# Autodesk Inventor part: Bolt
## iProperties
Shininess: 77.0
Length Units: 11269
Angle Units: 11279
Time Units: 11290
Mass Units: 11283
Length Display Precision: 3
Angle Display Precision: 2
Created: 2002-02
Part Number: Bolt
Document SubType Name: Modeling
Designer: ***
Stock Number: 25
Density: 0.0
Volumn: 0.0
Area: 0.0
PropertySet Name: Model Information
Control State: 0
Master: False
Checked Out: False
Author: ***
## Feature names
1. Extrusion1
2. Fillet1
3. Extrusion2
4. Extrusion3
